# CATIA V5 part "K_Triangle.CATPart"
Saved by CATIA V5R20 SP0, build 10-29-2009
Part number: Triangle
Property "Diamètre joint": 20 mm
Property "Ecart tige": 200 mm
Bounding box of the stored display mesh (mm): x -136.383 to 102.656, y -19.997 to 202.115, z 0 to 20
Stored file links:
  C:\Users\thinkmotion1\Desktop\Khaled_IAO_Pack2\Problemes\IAO_2010_1405_jpalas\IAO_PALAS\Khaled_Palas\K_Triangle.CATPart
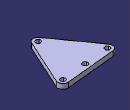
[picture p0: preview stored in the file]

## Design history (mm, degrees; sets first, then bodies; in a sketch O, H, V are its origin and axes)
Body1 (main body)
  Sketch1 on xy-plane, origin (0, 0, 0), H (1, 0, 0), V (0, 1, 0)
    arc A1 centre (0, 0) radius 20 from (-16.2646, -11.6388) to (18.2118, -8.2661) ccw
    arc A2 centre (82.6614, 182.1183) radius 20 from (100.8732, 173.8522) to (80.7142, 202.0233) ccw
    point P1 (82.6614, 182.1183)
    arc A3 centre (-116.3884, 162.6461) radius 20 from (-118.3356, 182.551) to (-132.653, 151.0072) ccw
    point P2 (-116.3884, 162.6461)
    line L1 (18.2118, -8.2661) -> (100.8732, 173.8522)
    line L2 (-132.653, 151.0072) -> (-16.2646, -11.6388)
    line L3 (-118.3356, 182.551) -> (80.7142, 202.0233)
    point P9 (33.8676, 147.2018)
    point P10 (-61.7529, 137.8476)
    point P11 (-5.8417, 59.7149)
    radius A2 = 20
    radius A3 = 20
    radius A1 = 20
    length L1 = 200
    length L3 = 200
    length L2 = 200
    distance P9 P1 = 60
    distance P10 P2 = 60
    distance P11 O = 60
    tangency: L1 A2, L1 A1, L2 A1, L2 A3, L3 A2, L3 A3
  Pad1: profile Sketch1, direction (0, 0, 1), length 20
  Sketch2 on start face of Pad1, origin (-113.0972, 158.4452, 0), H (1, 0, 0), V (0, -1, 0)
    point P1 (-3.2912, -4.2009)
    reference projected arc E1 centre (-3.2912, -4.2009) radius 20 from (-19.527, 7.4782) to (-5.2877, -24.101) ccw from edge [start face of Pad1 | face of Pad1 from Sketch1.A3]
    concentricity: P1 E1
  Hole1: placed by Sketch2, at (-116.3884, 162.6461, 0) direction (0, 0, 1), diameter 20, through (limit type 3)
  Sketch3 on start face of Pad1, origin (75.0999, 179.2646, 0), H (1, 0, 0), V (0, -1, 0)
    point P1 (7.5616, -2.8537)
    reference projected arc E1 centre (7.5616, -2.8537) radius 20 from (5.565, -22.7538) to (25.7938, 5.3673) ccw from edge [start face of Pad1 | face of Pad1 from Sketch1.A2]
    concentricity: P1 E1
  Hole2: placed by Sketch3, at (82.6614, 182.1183, 0) direction (0, 0, 1), diameter 20, through (limit type 3)
  Sketch4 on start face of Pad1, origin (-26.501, 20.2928, 0), H (1, 0, 0), V (0, -1, 0)
    point P1 (26.501, 20.2928)
    reference projected arc E1 centre (26.501, 20.2928) radius 20 from (44.7333, 28.5138) to (10.2653, 31.9719) ccw from edge [start face of Pad1 | face of Pad1 from Sketch1.A1]
    concentricity: P1 E1
  Hole3: placed by Sketch4, at (0, 0, 0) direction (0, 0, 1), diameter 20, through (limit type 3)
  Sketch5 on start face of Pad1, origin (-20.711, 174.446, 0), H (1, 0, 0), V (0, -1, 0)
    point P1 (3.8475, 2.0638)
    point P2 (-95.6774, 11.7999)
    reference projected circle E1 centre (-95.6774, 11.7999) radius 10 from edge [face of Hole1 | start face of Pad1]
    point P3 (103.3724, -7.6724)
    reference projected circle E2 centre (103.3724, -7.6724) radius 10 from edge [face of Hole2 | start face of Pad1]
    distance P1 P2 = 100
    distance P1 P3 = 100
    concentricity: P2 E1, P3 E2
  Hole4: placed by Sketch5, at (-16.8635, 172.3822, 0) direction (0, 0, 1), diameter 20, through (limit type 3)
